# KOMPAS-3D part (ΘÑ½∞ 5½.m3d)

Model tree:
1. Эскиз:1
2. Операция выдавливания:1
     Расстояние 1 = 2
3. Эскиз:2
4. Операция выдавливания:2
     Расстояние 1 = 5
5. Эскиз:3
6. Операция выдавливания:3
     Расстояние 1 = 2
7. Эскиз:4
8. Операция выдавливания:4
     Расстояние 1 = 78
9. Эскиз:5
10. Операция выдавливания:5
     Расстояние 1 = 2
11. Эскиз:6
12. Операция выдавливания:6
     Расстояние 1 = 4.5
13. Эскиз:7
14. Операция выдавливания:7
     Расстояние 1 = 2
15. Скругление:1
     Радиус = 1
16. Скругление:2
     Радиус = 1
17. Эскиз:8
18. Вырезать элемент выдавливания:1
     Расстояние 1 = 10; Угол 1 = 35
19. Эскиз:9
20. Вырезать элемент выдавливания:2
     Расстояние 1 = 10; Угол 1 = 35
21. Эскиз:10
22. Вырезать элемент выдавливания:3
     Расстояние 2 = 22; Расстояние 1 = 22; Угол 1 = 35
23. Эскиз:11
24. Вырезать элемент выдавливания:4
     Расстояние 2 = 2; Расстояние 1 = 2
25. Эскиз:12
26. Вырезать элемент выдавливания:5
     Расстояние 2 = 2; Расстояние 1 = 2; Угол 1 = 35
27. Эскиз:13
28. Вырезать элемент выдавливания:6
     Расстояние 2 = 2; Расстояние 1 = 122
29. Эскиз:14
30. Вырезать элемент выдавливания:7
     Расстояние 2 = 100; Расстояние 1 = 60
